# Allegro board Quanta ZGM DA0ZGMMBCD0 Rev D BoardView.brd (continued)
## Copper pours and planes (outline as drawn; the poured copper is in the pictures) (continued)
N82537287 on BOTTOM (solid shape): 208.06,179.45 208.06,178.78 207.98,178.7 207.68,178.7 207.11,178.13 207.11,177.92 207.12,177.91 207.12,176.57 207.01,176.45 207.01,175.8 206.79,175.59 205.97,175.59 205.93,175.63 205.31,175.63 205.23,175.71 205.23,176.04 205.59,176.4 205.82,176.4 205.92,176.49 205.92,178.13 206.12,178.33 206.74,178.33 207.38,178.97 207.38,179.47 207.46,179.55 207.96,179.55
N82537484 on TOP (solid shape): 209.63,184.93 209.63,183.98 209.09,183.43 209.09,182.25 208.48,181.64 206.71,181.64 206.45,181.9 206.45,182.51 206.74,182.81 206.74,183.41 206.79,183.46 206.99,183.46 207.07,183.39 207.05,183.33 207.05,183.27 207.44,182.88 208.45,183.88 208.45,184.76 208.75,185.06 209.5,185.06
N82537584 on TOP (solid shape): 211.19,182.71 211.19,182.25 210.94,182.01 210.54,182.01 210.36,181.83 210.36,180.92 210.18,180.73 209.42,180.73 209.35,180.8 209.35,182.03 209.52,182.2 210.09,182.2 210.47,182.58 210.47,182.83 210.54,182.9 210.99,182.9
N82538045 on BOTTOM (solid shape): 200.69,184.27 200.69,183 201.07,182.62 201.14,182.62 201.2,182.6 201.25,182.6 201.3,182.6 201.35,182.62 202.26,182.62 202.31,182.56 202.31,181.98 202.29,181.96 201.43,181.96 201.31,182.08 200.68,182.08 200.38,182.38 199.32,182.38 199.24,182.3 199.24,182.3 199.16,182.22 198.72,182.22 198.61,182.33 198.61,183.16 198.67,183.16 198.76,183.2 198.81,183.3 198.81,184.67 198.8,184.71 198.79,184.74 198.77,184.78 198.91,184.92 200.04,184.92
N82538267 on BOTTOM (solid shape): 200.41,186.79 201.43,186.79 201.51,186.71 201.51,186.39 201.46,186.35 200.27,186.35 200.11,186.19 200.11,185.47 199.96,185.32 199.02,185.32 198.9,185.45 198.9,186.6 199.15,186.84 200.36,186.84
N82555593 on TOP (solid shape): 205.39,45.58 205.39,43.48 205.39,43.46 205.9,42.95 205.9,42.11 205.82,42.03 205.41,42.03 205.18,42.25 205.18,43.08 204.55,43.71 204.55,44.87 204.19,45.24 203.96,45.24 203.92,45.25 203.91,45.29 203.91,46.04 204.02,46.15 204.82,46.15
N82846357 on TOP (solid shape): 159.05,74.34 159.87,74.34 159.94,74.27 159.94,73.86 159.86,73.77 159.33,73.77 159.16,73.94 158.61,73.94 158.61,73.96 158.16,73.96 158.16,74.26 158.61,74.26 158.61,74.46 158.16,74.46 158.16,74.76 158.16,74.76 158.64,74.76
N82850388 on TOP (solid shape): 111.99,120.74 111.99,120.61 111.99,120.57 112.37,120.19 113.33,120.19 113.39,120.12 113.39,119.4 113.36,119.37 112.8,119.37 112.74,119.32 112.72,119.28 112.62,119.18 112.62,119.15 112.19,118.72 111.64,118.72 111.57,118.71 111.5,118.68 111.49,118.68 111.42,118.68 111.34,118.76 111.34,119.32 111.24,119.42 111.24,120.68 111.34,120.78 111.95,120.78
N82850432 on TOP (solid shape): 112.1,123.62 112.14,123.62 112.21,123.62 112.25,123.62 112.31,123.64 113.19,123.64 113.33,123.5 113.33,122.06 113.21,121.95 112.23,121.95 112.17,121.95 111.79,122.32 111.79,123.58 111.85,123.64 112.05,123.64
N82853033 on BOTTOM (solid shape): 115.1,132.35 115.1,130.89 114.76,130.55 112.32,130.55 112.24,130.63 112.24,131.64 112.55,131.95 112.55,131.96 112.78,132.19 113.14,132.19 113.37,131.95 113.74,131.95 113.85,132.06 113.85,132.34 113.88,132.37 115.08,132.37
N82853047 on BOTTOM (solid shape): 115.12,134.2 115.12,132.62 115.05,132.55 114.44,132.55 114.39,132.6 114.39,132.88 114.03,133.24 113.92,133.24 113.86,133.3 113.86,134.26 113.91,134.31 115.01,134.31
N83068063 on TOP (solid shape): 224.52,205.67 224.52,205.39 224.53,205.36 224.54,205.32 224.54,205.17 224.67,205.04 224.92,205.04 225.2,204.76 225.2,204.18 224.95,203.92 224.21,203.92 223.95,204.18 223.95,205.53 224.21,205.78 224.41,205.78
N83075521 on TOP (solid shape): 287.78,122.43 287.81,122.42 287.83,122.38 287.83,122.23 287.81,122.19 287.78,122.18 287.01,122.18 287.01,121.98 287.78,121.98 287.81,121.97 287.83,121.93 287.83,121.78 287.81,121.74 287.78,121.73 287.01,121.73 287.01,121.53 287.64,121.53 287.73,121.47 287.71,121.36 286.88,120.53 286.88,120.3 287.53,119.65 287.63,119.65 287.66,119.63 287.68,119.6 287.68,118.68 287.6,118.6 284.45,118.6 284.38,118.68 284.38,119.61 284.89,120.12 284.89,120.52 284.7,120.71 284.44,120.71 284.36,120.79 284.36,121.57 284.33,121.6 284.33,121.62 284.72,122.01 286.57,122.01 286.99,122.43
N83075521 on BOTTOM (solid shape): 286.87,121.8 286.87,120.04 285.99,119.16 284.72,119.16 284.6,119.29 284.6,119.7 284.85,119.95 284.85,120.51 284.65,120.71 284.21,120.71 284.12,120.81 284.12,121.61 284.57,122.07 286.6,122.07
N83075814 on TOP (solid shape): 290.22,121.5 290.22,121.27 290.2,121.25 290.2,120.56 290.5,120.26 290.5,120.03 290.68,119.85 290.68,119.47 290.6,119.39 290.22,119.39 290.07,119.55 289.31,119.55 289.28,119.57 289.28,119.77 289.64,120.13 289.64,121.2 289.39,121.45 289.39,121.48 289.4,121.52 289.44,121.53 290.2,121.53
N83076272 on TOP (solid shape): 288.24,134.35 288.24,130.82 287.71,130.29 282.96,130.29 282.85,130.4 282.85,133.84 283.72,134.71 287.89,134.71
N83076272 on BOTTOM (solid shape): 288.57,133.38 288.57,132.01 288.95,131.63 288.95,130.51 288.68,130.24 283.52,130.24 283.11,130.66 283.11,133.2 283.66,133.76 288.2,133.76
N83076272 on IN3 (solid shape): outline of 964 points within 283.19,117.51 291.65,133.44
N83081355 on BOTTOM (solid shape): 290.95,122.83 290.95,122.47 290.93,122.45 290.71,122.45 290.38,122.11 290.38,121.27 290.72,120.93 290.95,120.93 291.17,120.7 291.17,120.3 291.03,120.16 290,120.16 289.22,120.94 289.22,121.78 289.5,122.06 289.73,122.06 289.74,122.06 289.92,122.06 290.45,122.58 290.45,122.77 290.57,122.89 290.89,122.89
N83083660 on TOP (solid shape): 289.85,127.56 289.85,125.36 289.68,125.29 289.61,125.12 289.61,125.1 289,124.49 288.98,124.49 288.72,124.37 288.6,124.11 288.6,124.09 288.5,123.99 288.5,122.89 288.5,122.88 288.3,122.88 288.27,122.9 288.25,122.93 288.25,123.68 288.05,123.68 288.05,122.93 288.04,122.9 288,122.88 287.95,122.88 287.67,123.17 287.05,123.17 286.59,123.64 286.26,123.64 286.19,123.71 286.19,123.99 285.8,124.37 285.8,126.22 287.34,127.76 289.66,127.76
N83083660 on BOTTOM (solid shape): 290.31,127.42 290.31,125.8 289.14,124.64 288.98,124.64 288.16,123.82 284.39,123.82 284.09,124.12 284.09,126.66 284.49,127.06 286.63,127.06 287.33,127.76 289.97,127.76
N83085661 on TOP (solid shape): 301.45,107.25 301.45,104.59 301.17,104.31 301.17,103.52 301.55,103.14 301.55,102.2 301.27,101.92 300.67,101.92 300.53,102.05 300.53,103.12 300.21,103.44 299.22,103.44 299.01,103.65 299.01,103.68 299.94,103.68 299.94,103.88 299.15,103.88 299.15,103.68 299.01,103.68 299.01,104.13 299.94,104.13 299.94,104.33 299.14,104.33 299.14,104.13 299.01,104.13 299.01,104.33 299.7,105.02 299.7,106.08 299.52,106.26 298.32,106.26 298.2,106.38 298.2,107.2 298.36,107.37 301.34,107.37
N83085661 on BOTTOM (solid shape): 301.51,105.81 301.51,102.36 301.33,102.19 300.6,102.19 300.05,102.74 300.05,105.78 300.35,106.08 301.23,106.08
N83085803 on TOP (solid shape): 300.12,103.13 300.12,101.93 300.01,101.82 299.59,101.82 299.43,101.98 299.43,102.92 299.37,102.99 299.29,102.99 299.14,103.14 299.14,103.21 299.16,103.23 300.02,103.23
N83085807 on TOP (solid shape): 299.15,102.85 299.15,101.75 299.44,101.47 300.14,101.47 300.86,100.75 300.86,97.68 300.81,97.63 298.74,97.63 298.66,97.72 298.66,101.72 298.43,101.94 298.43,102.18 298.89,102.18 298.89,102.98 298.69,102.98 298.69,102.18 298.43,102.18 298.44,102.19 298.44,102.98 298.55,103.09 298.92,103.09
N83085819 on TOP (solid shape): 296.73,100.32 296.73,97.63 297.24,97.12 298.38,97.12 298.69,96.81 298.69,94.65 298.65,94.6 295.56,94.6 295.3,94.86 295.3,96.25 294.67,96.89 294.67,98.93 294.54,99.05 294.15,99.05 293.9,99.3 293.9,101.17 294.17,101.44 295.6,101.44
N83085819 on BOTTOM (solid shape): 294.51,102.62 294.52,102.62 294.59,102.56 294.59,102.51 294.59,102.51 294.59,102.45 294.77,102.27 295.86,102.27 296.19,101.95 296.19,101.42 296.57,101.03 296.57,97.63 296.39,97.45 295.05,97.45 294.85,97.65 294.85,98.51 294.84,98.52 294.84,98.76 294.55,99.05 294.21,99.05 294.18,99.08 294.05,99.08 293.7,99.43 293.7,101.67 293.7,101.67 293.7,102.47 293.87,102.63 294.5,102.63
N83085921 on TOP (solid shape): 294.72,103.44 295.05,103.44 295.18,103.32 295.18,102.58 295.07,102.48 294.8,102.48 294.72,102.4 294.72,102.34 294.71,102.32 294.7,102.29 294.7,101.91 294.71,101.88 294.72,101.85 294.72,101.79 294.67,101.74 294.03,101.74 293.89,101.89 293.89,103.63 294.08,103.82 294.34,103.82
N83092641 on TOP (solid shape): 73.16,53.15 73.16,52.39 73.03,52.26 71.74,52.26 71.67,52.33 69.76,52.33 69.6,52.49 69.6,53.18 69.62,53.2 69.8,53.2 69.8,52.49 70,52.49 70,53.2 70.23,53.2 70.23,53.19 71.53,53.19 71.64,53.3 73,53.3
N83092641 on TOP (solid shape): 67.09,53.2 67.8,53.2 67.8,52.49 68,52.49 68,53.2 68.19,53.2 68.2,53.18 68.2,52.48 67.93,52.21 67.93,51.99 67.57,51.63 67.21,51.63 67.08,51.5 67.08,51.19 67.07,51.18 67.07,50.98 66.88,50.79 66.42,50.79 66.27,50.94 66.27,51.4 65.99,51.68 65.99,53.2 66.04,53.25 67.03,53.25
N83179814 on TOP (solid shape): 287.09,122.9 287.66,122.9 287.79,122.77 287.79,122.67 287.76,122.65 286.3,122.65 285.85,122.2 285.19,122.2 285.04,122.35 285.04,122.93 285.29,123.19 286.8,123.19
N83179815 on TOP (solid shape): 285.9,124.04 285.9,123.69 285.74,123.54 285.23,123.54 284.8,123.11 284.8,122.53 284.38,122.11 283.85,122.11 283.64,122.32 283.64,122.97 284.84,124.16 285.77,124.16
N83379619 on BOTTOM (solid shape): 194.9,166.59 194.9,165.85 195.96,164.78 195.96,164 195.79,163.82 195.33,163.82 194.97,164.17 193.65,164.17 193.6,164.22 193.6,164.99 193.31,165.28 192.8,165.28 191.98,166.1 191.98,166.38 192.06,166.47 192.08,166.48 192.12,166.47 192.5,166.47 192.52,166.47 192.56,166.49 192.89,166.49 193.45,167.04 194.44,167.04
N83379972 on BOTTOM (solid shape): 191.24,166.1 191.24,165.24 192,164.48 192.38,164.48 192.74,164.12 192.74,163.44 192.43,163.13 191.62,163.13 190.78,163.97 189.64,163.97 189.11,164.5 189.11,166.05 189.23,166.18 190.15,166.18 190.35,166.38 190.96,166.38
N84112222 on BOTTOM (solid shape): 244.94,219.55 244.94,215.94 245.24,215.63 247.17,215.63 247.42,215.38 247.42,215.23 247.32,215.13 244.99,215.13 244.38,215.74 244.38,217.26 244.22,217.41 244.22,219.8 244.68,219.8
N84917166 on TOP (solid shape): 56.8,70.45 57,70.45 57,71.16 57.23,71.16 57.43,70.96 58.4,70.96 58.47,70.88 58.47,70.08 58.08,69.69 58.08,68.41 58.01,68.35 56.94,68.35 56.88,68.41 56.88,69.51 56.63,69.77 56.63,70.42 56.6,70.45 56.6,71.13 56.62,71.16 56.8,71.16
N84917166 on TOP (solid shape): 54.8,70.45 55,70.45 55,71.17 55.2,71.17 55.2,71.16 55.2,70.45 54.63,69.88 53.33,69.88 53.14,69.68 52.74,69.68 52.73,69.7 52.68,69.72 52.63,69.73 51.29,69.73 51.08,69.94 51.08,70.7 51.26,70.88 53.28,70.88 53.29,70.89 53.73,70.89 54.01,71.17 54.8,71.17
N85188370 on BOTTOM (solid shape): 284.52,205.68 284.61,205.66 284.7,205.68 284.71,205.68 284.86,205.68 285.23,205.32 285.28,205.31 285.31,205.31 285.39,205.31 285.45,205.29 285.5,205.28 285.76,205.28 285.8,205.24 285.8,204.81 285.56,204.57 284.34,204.57 283.32,203.55 281.89,203.55 281.64,203.8 281.64,204.6 282.72,205.68 284.51,205.68
N90352201 on TOP (solid shape): 62.9,67.53 62.9,64.86 62.78,64.73 61.6,64.73 61.47,64.86 61.47,67.55 61.55,67.63 62.8,67.63
N852184901 on BOTTOM (solid shape): 205.59,182.73 205.59,181.56 205.85,181.3 206.44,181.3 206.54,181.21 206.54,180.33 206.49,180.28 205.02,180.28 204.84,180.46 204.84,181.16 205.13,181.46 205.13,182.73 205.22,182.81 205.51,182.81

Small or netless copper shapes (teardrops, artwork), in the pictures only: 291 on TOP, 40 on BOTTOM, 44 on IN1, 96 on IN2, 27 on IN3, 1 on IN4

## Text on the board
Ref Des/Silkscreen Bottom: Please do not print out the lines with 0.39mils/0.01mm in width | MODEL:ZGM | DA0ZGMMBCD0 REV:D | 2 | 1
User.Comments: 16x28 | 24x63 | 28x94 | 26x114 | 28x169
Ref Des/Silkscreen Top: Please do not print out the lines with 0.39mils/0.01mm in width | DA0ZGMMBCD0 REV:D
User.12: +USBPWR3 | TYPEC1_USB0 | +5VPCU | GND | +VIN | +3V | +VCC_CORE | +VCCIN_AUX | +19V_VIN1 | +VIN_VGACORE | +FBVDDQ_MEM | +19V_VIN2 | +VIN_GPU_TOTAL | NVVDD | +5V | ADOGND
User.24: GND | +USBPWR3 | +3V | TYPEC2_USB0 | +VIN | +VCC_CORE | +5VPCU | +VCCIN_AUX | +VGPU_SRC_R | +5V | +VIN_VGACORE | +FBVDDQ_MEM | +VIN_GPU_TOTAL | NVVDD | +3V_S5 | ADOGND
User.25: NVVDD | GND | ADOGND
User.26: GND | ADOGND
User.27: GND | ADOGND
User.28: GND | ADOGND
User.45: XY-Check acute:Jan 28 13:57:38 2021 | XY-Create nettxt:Dec 08 12:59:56 2020 | XY-Create plane:Jan 28 12:40:47 2021 | XY-Cross plane-BOTTOM-SGND3:Jan 28 14:01:56 2021 | XY-Cross plane-IN1-SGND1:Jan 28 14:00:13 2021 | XY-Cross plane-IN1-SGND:Jan 28 14:00:20 2021 | XY-Cross plane-IN2-SGND1:Jan 28 14:00:43 2021 | XY-Cross plane-IN2-SVCC:Jan 28 14:00:29 2021 | XY-Cross plane-IN3-SGND2:Jan 28 14:00:54 2021 | XY-Cross plane-IN3-SVCC1:Jan 28 14:01:03 2021 | XY-Cross plane-IN4-SGND2:Jan 28 14:01:37 2021 | XY-Cross plane-IN4-SGND3:Jan 28 14:01:17 2021 | XY-Cross plane-TOP-SGND:Jan 28 14:00:02 2021 | XY-Dxf to pin check:Jan 28 12:39:18 2021 | XY-Etch ref-BOTTOM-SGND3:Jan 28 14:02:33 2021 | XY-Etch ref-IN1-SGND1:Jan 28 14:00:19 2021 | XY-Etch ref-IN1-SGND:Jan 28 14:00:28 2021 | XY-Etch ref-IN2-SGND1:Jan 28 14:00:54 2021 | XY-Etch ref-IN2-SVCC:Jan 28 14:00:42 2021 | XY-Etch ref-IN3-SGND2:Jan 28 14:01:03 2021 | XY-Etch ref-IN3-SVCC1:Jan 28 14:01:16 2021 | XY-Etch ref-IN4-SGND2:Jan 28 14:01:55 2021 | XY-Etch ref-IN4-SGND3:Jan 28 14:01:36 2021 | XY-Etch ref-TOP-SGND:Jan 28 14:00:12 2021 | XY-Excess check:Jan 28 13:48:16 2021 | XY-Outline check:Jan 28 14:06:40 2021 | XY-PadStack_Check:Jan 28 13:47:24 2021 | XY-Plane net check:Jan 28 12:41:33 2021 | XY-Prop check:Jan 28 13:59:47 2021 | XY-shape min check:Jan 28 12:37:11 2021 | XY-via check:Jan 28 14:03:54 2021 | FIGURE | TYPE | Oblong | Circle | SIZE | 59.0x35.0 | 67.0x28.0 | 73.0x22.0 | 75.0x31.0 | 79.0x31.0 | 98.0x35.0 | 10.0 | 12.0 | 14.0 | 22.0 | 32.0 | 79.0 | 118.0 | 134.0 | 146.0 | 158.0 | 276.0 | 30.0 | 38.0 | 41.0 | 47.0 | 67.0 | 71.0 | 110.0 | 114.0 | DRILL CHART: TOP to BOTTOM | ALL UNITS ARE IN MILS | PLATED | NON-PLATED | ROTATION | 90.000 | 0.000 | - | QTY | 4 | 2 | 8 | 42 | 10705 | 13 | 2515 | 29 | 9 | 14 | 3 | 1 | 6 | 13333 | TOTAL HOLES:
